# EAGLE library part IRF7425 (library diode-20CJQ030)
International Rectifier's IRF7425 HEXFET® Power MOSFET Description: These P-Channel MOSFETs from International Rectifier utilize advanced processing techniques to achieve the extremely low on-resistance per silicon area. This benefit provides the designer with an extremely efficient device for use in battery and load management applications.. The SO-8 has been modified through a customized leadframe for enhanced thermal characteristics and multiple-die capability making it ideal in a variety of power applications. With these improvements, multiple devices can be used in an application with dramatically reduced board space. The package is designed for vapor phase, infrared, or wave soldering techniques. Features: Ultra Low On-Resistance P Channel MOSFET Surface Mount Available in Tape & Reel Please send any comments to: messi@users.sourceforge.net
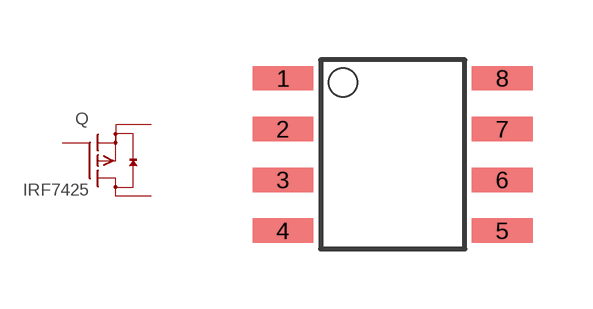
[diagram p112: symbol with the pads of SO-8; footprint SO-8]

Designator prefix Q

## IRF7425  [SO-8]
1  S  pas
2  S  pas
3  S  pas
4  G  pas
5  D  pas
6  D  pas
7  D  pas
8  D  pas

## Footprint SO-8 (pad centres in mm)
small outline
smd 1.524 x 0.61: 1 -2.743,1.27; 2 -2.743,0; 3 -2.743,-1.27; 4 -2.743,-2.54; 5 2.743,-2.54; 6 2.743,-1.27; 7 2.743,0; 8 2.743,1.27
